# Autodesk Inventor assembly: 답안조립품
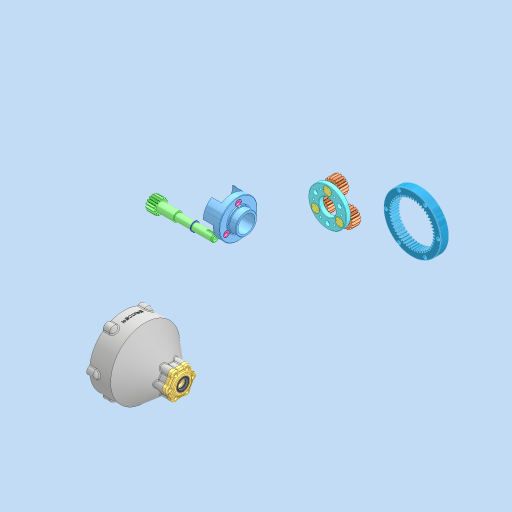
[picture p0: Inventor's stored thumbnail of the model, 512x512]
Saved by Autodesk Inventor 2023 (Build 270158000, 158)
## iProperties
Created: 2026-05
Part Number: 답안조립품
Document SubType Name: Assembly
Designer: home
Author: home
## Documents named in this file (16)
- C:\Users\home\Desktop\760503v1006\답안조립품.iam
- C:\Users\home\Desktop\760503v1006\본체.ipt
- C:\Users\home\Desktop\760503v1006\깊은 홈 볼 베어링 6203.ipt
- C:\Users\home\Desktop\760503v1006\선 기어 축.ipt
- C:\Users\home\Desktop\760503v1006\축용 C형 멈춤링 17.ipt
- C:\Users\home\Desktop\760503v1006\커버.ipt
- C:\Users\home\Desktop\760503v1006\오일 실 17 32 8.ipt
- C:\Users\home\Desktop\760503v1006\깊은 홈 볼 베어링 6010.ipt
- C:\Users\home\Desktop\760503v1006\유성 캐리어.ipt
- C:\Users\home\Desktop\760503v1006\엔드 캡.ipt
- C:\Users\home\Desktop\760503v1006\칼라.ipt
- C:\Users\home\Desktop\760503v1006\유성 캐리어 커버.ipt
- C:\Users\home\Desktop\760503v1006\유성 축.ipt
- C:\Users\home\Desktop\760503v1006\유성 기어.ipt
- C:\Users\home\Desktop\760503v1006\깊은 홈 볼 베어링 6900.ipt
- C:\Users\home\Desktop\760503v1006\링 기어.ipt
